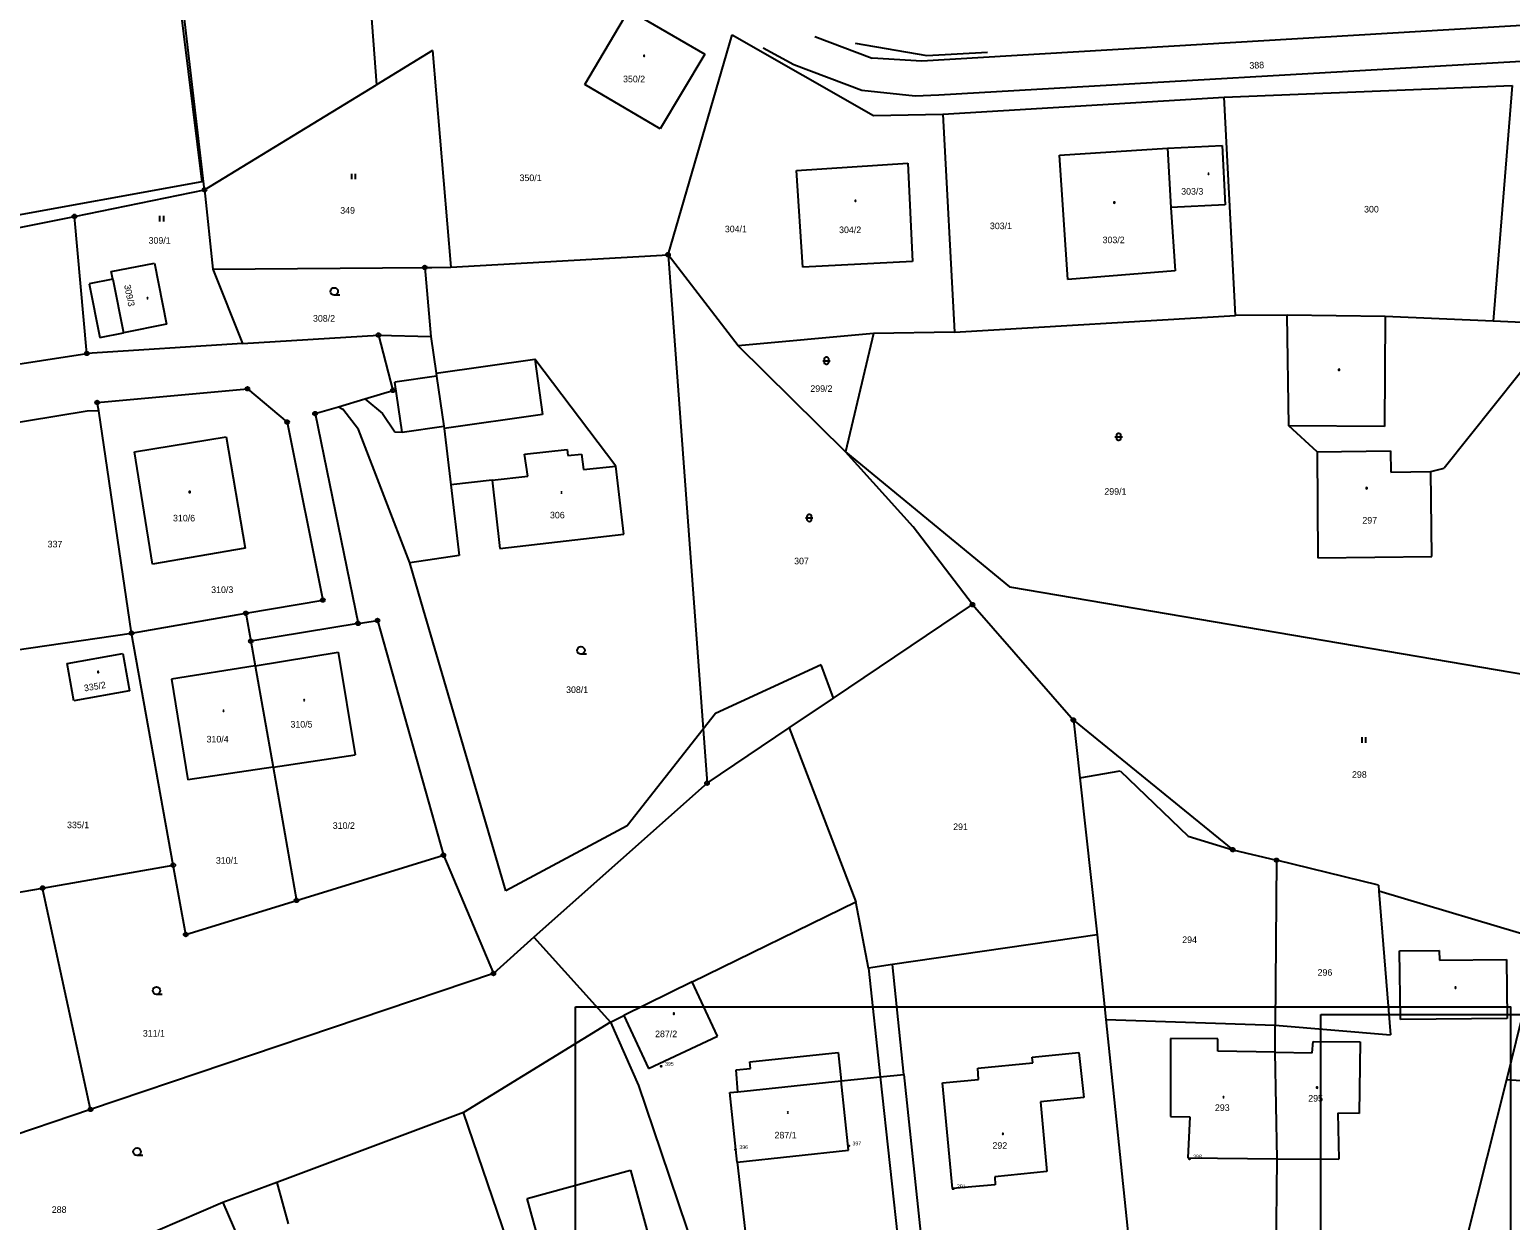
# Model space of a CAD drawing. Extents: x -454285 to -453563, y -1108687 to -1108249.
# Drawn here: x -454026.3 to -453869.2, y -1108463.6 to -1108337.2 of the extents above; entities that cross this region are included whole.
import ezdxf

# ---------------------------------------------------------------- set-up
doc = ezdxf.new("R2010")
doc.units = 0
for name, color, linetype in [('1', 7, 'Continuous'), ('14', 7, 'Continuous'), ('15', 7, 'Continuous'), ('16', 7, 'Continuous'), ('2', 7, 'Continuous'), ('23', 7, 'Continuous'), ('25', 7, 'Continuous'), ('28', 7, 'Continuous'), ('BODY_T1_2018', 7, 'Continuous'), ('CISLA_T1_2018', 7, 'Continuous'), ('rámy', 7, 'Continuous')]:
    doc.layers.add(name, color=color, linetype=linetype)

# ---------------------------------------------------------------- blocks, each defined once
blk = doc.blocks.new('Z402')
for start, end in [(0, 180), (180, 0)]:
    blk.add_arc((0, 0), 0.15, start, end)
blk = doc.blocks.new('Z105')
for radius in [0.5, 0.01]:
    blk.add_circle((0, 0), radius)
blk = doc.blocks.new('Z3040')
blk.add_line((1.5, 0), (0, 0))
blk.add_circle((0, 1), 1)
blk = doc.blocks.new('Z3060')
for p, q in [((-0.5, 1.5), (-0.5, 0)), ((0.5, 1.5), (0.5, 0))]:
    blk.add_line(p, q)
blk = doc.blocks.new('Z3160')
for p, q in [((-1, 1), (1, 1)), ((-0.5, 1.6), (-0.4, 1.8)), ((-0.5, 0.4), (-0.5, 1.6)), ((-0.4, 0.2), (-0.5, 0.4)), ((-0.4, 1.8), (-0.3, 1.9)), ((-0.3, 0.1), (-0.4, 0.2)), ((-0.3, 1.9), (-0.1, 2)), ((-0.1, 0), (-0.3, 0.1)), ((-0.1, 2), (0.1, 2)), ((0.1, 0), (-0.1, 0)), ((0.1, 2), (0.3, 1.9)), ((0.3, 0.1), (0.1, 0)), ((0.3, 1.9), (0.4, 1.8)), ((0.4, 0.2), (0.3, 0.1)), ((0.4, 1.8), (0.5, 1.6)), ((0.5, 0.4), (0.4, 0.2)), ((0.5, 1.6), (0.5, 0.4))]:
    blk.add_line(p, q)
blk = doc.blocks.new('POINT_DISPLAY')
for p, q in [((-0.1, 0), (0.1, 0)), ((0, -0.1), (0, 0.1))]:
    blk.add_line(p, q)
blk.add_circle((0, 0), 0.05)
blk = doc.blocks.new('t1_2018')
at = {"layer": 'BODY_T1_2018'}
for p in [(-453959.29, -1108447.2), (-453951.4, -1108456.05), (-453939.4, -1108455.65), (-453903.26, -1108457.04), (-453928.32, -1108460.2)]:
    blk.add_blockref('POINT_DISPLAY', p, dxfattribs=at)
at = {"layer": 'CISLA_T1_2018'}
for s, p in [('395', (-453958.89, -1108447.14)), ('397', (-453939, -1108455.59)), ('396', (-453951, -1108455.99)), ('398', (-453902.86, -1108456.98)), ('201', (-453927.92, -1108460.14))]:
    blk.add_text(s, height=0.4, dxfattribs=at).set_placement(p)

msp = doc.modelspace()

# ---------------------------------------------------------------- linework, layer by layer
at = {"layer": '1'}
for p, q in [((-454007.73, -1108354.18), (-454012.57, -1108313.19)), ((-453990.72, -1108326.88), (-453989.5, -1108343.02)), ((-453967.38, -1108342.99), (-453962.71, -1108335.1)), ((-453962.71, -1108335.1), (-453954.65, -1108339.78)), ((-453958.57, -1108361.06), (-453951.77, -1108337.73)), ((-453951.77, -1108337.73), (-453936.77, -1108346.27)), ((-453938.72, -1108338.62), (-453931.11, -1108339.92)), ((-453983.57, -1108339.38), (-453989.5, -1108343.02)), ((-453983.57, -1108339.38), (-453981.6, -1108362.39)), ((-453954.65, -1108339.78), (-453959.4, -1108347.71)), ((-453931.11, -1108339.92), (-453924.66, -1108339.55)), ((-454007.73, -1108354.18), (-453989.5, -1108343.02)), ((-453959.4, -1108347.71), (-453967.38, -1108342.99)), ((-453899.58, -1108344.34), (-453869.02, -1108343.11)), ((-453869.02, -1108343.11), (-453871.03, -1108368.12)), ((-453929.41, -1108346.16), (-453899.58, -1108344.34)), ((-453898.37, -1108367.53), (-453899.58, -1108344.34)), ((-453936.77, -1108346.27), (-453929.41, -1108346.16)), ((-453929.41, -1108346.16), (-453928.17, -1108369.27)), ((-453917.03, -1108350.48), (-453905.58, -1108349.76)), ((-453905.58, -1108349.76), (-453899.77, -1108349.48)), ((-453905.58, -1108349.76), (-453905.22, -1108356.05)), ((-453899.77, -1108349.48), (-453899.45, -1108355.77)), ((-453944.94, -1108352.11), (-453933.12, -1108351.33)), ((-453933.12, -1108351.33), (-453932.65, -1108361.78)), ((-453916.15, -1108363.7), (-453917.03, -1108350.48)), ((-453944.27, -1108362.38), (-453944.94, -1108352.11)), ((-454021.54, -1108356.99), (-454007.73, -1108354.18)), ((-454007.73, -1108354.18), (-454006.85, -1108362.58)), ((-453899.45, -1108355.77), (-453905.22, -1108356.05)), ((-453905.22, -1108356.05), (-453904.77, -1108362.76)), ((-454045.66, -1108361.88), (-454021.54, -1108356.99)), ((-454020.21, -1108371.54), (-454021.54, -1108356.99)), ((-454017.64, -1108362.85), (-454013.04, -1108361.95)), ((-454013.04, -1108361.95), (-454011.76, -1108368.45)), ((-454006.85, -1108362.58), (-453984.38, -1108362.42)), ((-453984.38, -1108362.42), (-453983.63, -1108362.41)), ((-453984.38, -1108362.42), (-453983.74, -1108369.73)), ((-453983.63, -1108362.41), (-453981.6, -1108362.39)), ((-453981.6, -1108362.39), (-453958.57, -1108361.06)), ((-453951.11, -1108370.72), (-453958.57, -1108361.06)), ((-453958.57, -1108361.06), (-453954.85, -1108411.41)), ((-453932.65, -1108361.78), (-453944.27, -1108362.38)), ((-454017.48, -1108363.65), (-454019.99, -1108364.16)), ((-454017.48, -1108363.65), (-454017.64, -1108362.85)), ((-454006.85, -1108362.58), (-454003.7, -1108370.5)), ((-453904.77, -1108362.76), (-453916.15, -1108363.7)), ((-454019.99, -1108364.16), (-454018.83, -1108369.84)), ((-454011.76, -1108368.45), (-454016.34, -1108369.37)), ((-453928.17, -1108369.27), (-453898.37, -1108367.53)), ((-453892.89, -1108367.48), (-453898.37, -1108367.53)), ((-453882.49, -1108367.62), (-453892.89, -1108367.48)), ((-453892.7, -1108379.24), (-453892.89, -1108367.48)), ((-453871.03, -1108368.12), (-453882.49, -1108367.62)), ((-453864.04, -1108368.42), (-453876.25, -1108383.71)), ((-454018.83, -1108369.84), (-454016.34, -1108369.37)), ((-454003.7, -1108370.5), (-453989.28, -1108369.59)), ((-453989.28, -1108369.59), (-453983.74, -1108369.73)), ((-453989.28, -1108369.59), (-453987.75, -1108375.46)), ((-453936.76, -1108369.43), (-453951.11, -1108370.72)), ((-453936.76, -1108369.43), (-453939.73, -1108381.98)), ((-453928.17, -1108369.27), (-453936.76, -1108369.43)), ((-454082.44, -1108381.06), (-454020.21, -1108371.54)), ((-454003.7, -1108370.5), (-454020.21, -1108371.54)), ((-453939.73, -1108381.98), (-453951.11, -1108370.72)), ((-453983.18, -1108373.64), (-453972.71, -1108372.15)), ((-453964.1, -1108383.52), (-453972.71, -1108372.15)), ((-453983.14, -1108373.94), (-453987.54, -1108374.58)), ((-453986.78, -1108379.9), (-453987.54, -1108374.58)), ((-453983.18, -1108373.64), (-453983.14, -1108373.94)), ((-454019.13, -1108376.75), (-454003.17, -1108375.29)), ((-454003.17, -1108375.29), (-453998.97, -1108378.82)), ((-453993.52, -1108377.19), (-453990.72, -1108376.35)), ((-453990.72, -1108376.35), (-453987.75, -1108375.46)), ((-453990.72, -1108376.35), (-453988.86, -1108377.9)), ((-454020.2, -1108377.66), (-454048.37, -1108382.31)), ((-454018.94, -1108377.64), (-454020.2, -1108377.66)), ((-454018.94, -1108377.64), (-454019.13, -1108376.75)), ((-454015.47, -1108401.22), (-454018.94, -1108377.64)), ((-453996.01, -1108377.93), (-453993.52, -1108377.19)), ((-453996.01, -1108377.93), (-453991.45, -1108400.19)), ((-453993.52, -1108377.19), (-453993.07, -1108377.45)), ((-453991.41, -1108379.6), (-453993.07, -1108377.45)), ((-453988.86, -1108377.9), (-453987.56, -1108379.86)), ((-453998.97, -1108378.82), (-453995.19, -1108397.71)), ((-453985.96, -1108393.75), (-453991.41, -1108379.6)), ((-453889.72, -1108381.97), (-453892.7, -1108379.24)), ((-454015.17, -1108381.98), (-454005.44, -1108380.38)), ((-454005.44, -1108380.38), (-454003.41, -1108392.2)), ((-453987.56, -1108379.86), (-453986.78, -1108379.9)), ((-454013.27, -1108393.89), (-454015.17, -1108381.98)), ((-453939.73, -1108381.98), (-453922.36, -1108396.3)), ((-453932.58, -1108389.95), (-453939.73, -1108381.98)), ((-453889.72, -1108381.97), (-453889.65, -1108393.25)), ((-453963.27, -1108390.72), (-453964.1, -1108383.52)), ((-453877.66, -1108384.07), (-453876.25, -1108383.71)), ((-453877.53, -1108393.08), (-453877.66, -1108384.07)), ((-453977.24, -1108384.99), (-453981.61, -1108385.48)), ((-453981.61, -1108385.48), (-453980.73, -1108392.98)), ((-453977.24, -1108384.99), (-453976.4, -1108392.24)), ((-453976.4, -1108392.24), (-453963.27, -1108390.72)), ((-453926.27, -1108398.2), (-453932.58, -1108389.95)), ((-454003.41, -1108392.2), (-454013.27, -1108393.89)), ((-453980.73, -1108392.98), (-453985.96, -1108393.75)), ((-453889.65, -1108393.25), (-453877.53, -1108393.08)), ((-453922.36, -1108396.3), (-453863.2, -1108406.37)), ((-454003.35, -1108399.12), (-453995.19, -1108397.71)), ((-453941.01, -1108408.12), (-453926.27, -1108398.2)), ((-453926.27, -1108398.2), (-453915.57, -1108410.45)), ((-454015.47, -1108401.22), (-454003.35, -1108399.12)), ((-454003.35, -1108399.12), (-454002.83, -1108402.07)), ((-453991.45, -1108400.19), (-454002.83, -1108402.07)), ((-453991.45, -1108400.19), (-453989.38, -1108399.89)), ((-453989.38, -1108399.89), (-453982.4, -1108424.79)), ((-454044.83, -1108405.52), (-454015.47, -1108401.22)), ((-454011.05, -1108425.86), (-454015.47, -1108401.22)), ((-454022.31, -1108404.45), (-454016.4, -1108403.39)), ((-454016.4, -1108403.39), (-454015.69, -1108407.36)), ((-454002.83, -1108402.07), (-454002.37, -1108404.69)), ((-454002.37, -1108404.69), (-453993.55, -1108403.25)), ((-453993.55, -1108403.25), (-453991.74, -1108414.13)), ((-454021.6, -1108408.41), (-454022.31, -1108404.45)), ((-454002.37, -1108404.69), (-454011.24, -1108406.13)), ((-454002.37, -1108404.69), (-454000.47, -1108415.44)), ((-454011.24, -1108406.13), (-454009.49, -1108416.78)), ((-454015.69, -1108407.36), (-454021.6, -1108408.41)), ((-453945.72, -1108411.29), (-453941.01, -1108408.12)), ((-453915.57, -1108410.45), (-453914.89, -1108416.57)), ((-453915.57, -1108410.45), (-453898.66, -1108424.21)), ((-453954.85, -1108411.41), (-453954.43, -1108417.15)), ((-453954.43, -1108417.15), (-453945.72, -1108411.29)), ((-453945.72, -1108411.29), (-453938.63, -1108429.73)), ((-454000.47, -1108415.44), (-453991.74, -1108414.13)), ((-454000.47, -1108415.44), (-454009.49, -1108416.78)), ((-454000.47, -1108415.44), (-453997.98, -1108429.59)), ((-453954.43, -1108417.15), (-453972.79, -1108433.51)), ((-453914.89, -1108416.57), (-453913.03, -1108433.25)), ((-453997.98, -1108429.59), (-453982.4, -1108424.79)), ((-453982.4, -1108424.79), (-453977.09, -1108437.35)), ((-453898.66, -1108424.21), (-453894.01, -1108425.33)), ((-453894.01, -1108425.33), (-453894.15, -1108442.84)), ((-453883.2, -1108427.98), (-453894.01, -1108425.33)), ((-454024.91, -1108428.28), (-454011.05, -1108425.86)), ((-454009.73, -1108433.21), (-454011.05, -1108425.86)), ((-454040.76, -1108431.04), (-454024.91, -1108428.28)), ((-454019.82, -1108451.78), (-454024.91, -1108428.28)), ((-453883.2, -1108427.98), (-453883.15, -1108428.6)), ((-454009.73, -1108433.21), (-453997.98, -1108429.59)), ((-453956, -1108438.24), (-453938.63, -1108429.73)), ((-453937.31, -1108436.78), (-453938.63, -1108429.73)), ((-453865.89, -1108433.79), (-453883.15, -1108428.6)), ((-453883.15, -1108428.6), (-453881.93, -1108443.86)), ((-453913.03, -1108433.25), (-453934.77, -1108436.41)), ((-453913.03, -1108433.25), (-453912.11, -1108442.25)), ((-453972.79, -1108433.51), (-453977.09, -1108437.35)), ((-453977.09, -1108437.35), (-454019.82, -1108451.78)), ((-453934.77, -1108436.41), (-453937.31, -1108436.78)), ((-453933.54, -1108448.06), (-453934.77, -1108436.41)), ((-453956, -1108438.24), (-453963.27, -1108441.81)), ((-453953.31, -1108444), (-453956, -1108438.24)), ((-453964.68, -1108442.51), (-453980.28, -1108452.1)), ((-453964.68, -1108442.51), (-453963.27, -1108441.81)), ((-453964.68, -1108442.51), (-453961.7, -1108449.25)), ((-453963.27, -1108441.81), (-453960.65, -1108447.43)), ((-453912.11, -1108442.25), (-453909.31, -1108469.46)), ((-453912.11, -1108442.25), (-453894.15, -1108442.84)), ((-453869.6, -1108448.59), (-453868.09, -1108442.55)), ((-453960.65, -1108447.43), (-453953.31, -1108444)), ((-453894.17, -1108445.7), (-453894.15, -1108442.84)), ((-453894.15, -1108442.84), (-453881.93, -1108443.86)), ((-453893.95, -1108457.01), (-453894.17, -1108445.7)), ((-453940.2, -1108448.76), (-453936.06, -1108448.32)), ((-453939.42, -1108456.12), (-453940.2, -1108448.76)), ((-453936.06, -1108448.32), (-453933.54, -1108448.06)), ((-453933.54, -1108448.06), (-453930.96, -1108472.62)), ((-453873.75, -1108465.15), (-453869.6, -1108448.59)), ((-453869.6, -1108448.59), (-453864.56, -1108448.98)), ((-453961.7, -1108449.25), (-453959.33, -1108456.23)), ((-454019.82, -1108451.78), (-454059.47, -1108465.16)), ((-453980.28, -1108452.1), (-454000.08, -1108459.53)), ((-453969.72, -1108482.96), (-453980.28, -1108452.1)), ((-453959.33, -1108456.23), (-453951.89, -1108478.2)), ((-453951.24, -1108457.36), (-453939.42, -1108456.12)), ((-453973.51, -1108461.22), (-453962.56, -1108458.21)), ((-453962.56, -1108458.21), (-453959.53, -1108469.18)), ((-453951.24, -1108457.36), (-453949.49, -1108472.34)), ((-453894.07, -1108467.77), (-453893.95, -1108457.01)), ((-454000.08, -1108459.53), (-454005.8, -1108461.67)), ((-454000.08, -1108459.53), (-453998.86, -1108463.94)), ((-453970.51, -1108472.16), (-453973.51, -1108461.22)), ((-454005.8, -1108461.67), (-454014.99, -1108465.61)), ((-454005.8, -1108461.67), (-454001.59, -1108471.32))]:
    msp.add_line(p, q, dxfattribs=at)
at = {"layer": '2'}
for p, q in [((-454018.02, -1108273.13), (-454008.01, -1108353.31)), ((-453863.12, -1108336.46), (-453931.66, -1108340.51)), ((-453943.01, -1108337.89), (-453936.91, -1108340.2)), ((-453945.22, -1108340.9), (-453948.48, -1108339.14)), ((-453931.66, -1108340.51), (-453936.91, -1108340.2)), ((-453866.21, -1108340.44), (-453929.83, -1108344.13)), ((-453938, -1108343.64), (-453945.22, -1108340.9)), ((-453932.35, -1108344.23), (-453938, -1108343.64)), ((-453929.83, -1108344.13), (-453932.35, -1108344.23)), ((-454008.01, -1108353.31), (-454045.52, -1108360.12)), ((-454017.48, -1108363.65), (-454016.34, -1108369.37)), ((-453882.49, -1108367.62), (-453882.58, -1108379.31)), ((-453864.04, -1108368.42), (-453871.03, -1108368.12)), ((-453983.74, -1108369.73), (-453983.18, -1108373.64)), ((-453972.71, -1108372.15), (-453971.87, -1108378.01)), ((-453983.14, -1108373.94), (-453982.36, -1108379.25)), ((-453971.87, -1108378.01), (-453982.33, -1108379.5)), ((-453986.78, -1108379.9), (-453982.36, -1108379.25)), ((-453982.36, -1108379.25), (-453982.33, -1108379.5)), ((-453982.33, -1108379.5), (-453981.61, -1108385.48)), ((-453882.58, -1108379.31), (-453892.7, -1108379.24)), ((-453973.78, -1108382.24), (-453969.27, -1108381.72)), ((-453973.44, -1108384.56), (-453973.78, -1108382.24)), ((-453969.27, -1108381.72), (-453969.19, -1108382.39)), ((-453969.19, -1108382.39), (-453967.74, -1108382.22)), ((-453967.74, -1108382.22), (-453967.55, -1108383.87)), ((-453889.72, -1108381.97), (-453881.92, -1108381.86)), ((-453881.92, -1108381.86), (-453881.89, -1108384.13)), ((-453977.24, -1108384.99), (-453973.44, -1108384.56)), ((-453967.55, -1108383.87), (-453964.1, -1108383.52)), ((-453881.89, -1108384.13), (-453877.66, -1108384.07)), ((-453984.74, -1108397.92), (-453985.96, -1108393.75)), ((-453975.77, -1108428.58), (-453984.74, -1108397.92)), ((-453942.33, -1108404.6), (-453953.54, -1108409.74)), ((-453941.01, -1108408.12), (-453942.33, -1108404.6)), ((-453953.54, -1108409.74), (-453954.85, -1108411.41)), ((-453954.85, -1108411.41), (-453962.91, -1108421.67)), ((-453914.89, -1108416.57), (-453910.59, -1108415.84)), ((-453910.59, -1108415.84), (-453903.4, -1108422.78)), ((-453962.91, -1108421.67), (-453975.77, -1108428.58)), ((-453903.4, -1108422.78), (-453898.66, -1108424.21)), ((-453972.79, -1108433.51), (-453964.68, -1108442.51)), ((-453880.96, -1108434.95), (-453876.75, -1108434.91)), ((-453880.88, -1108442.25), (-453880.96, -1108434.95)), ((-453876.75, -1108434.91), (-453876.73, -1108435.94)), ((-453876.73, -1108435.94), (-453869.61, -1108435.86)), ((-453869.61, -1108435.86), (-453869.54, -1108442.13)), ((-453937.31, -1108436.78), (-453936.06, -1108448.32)), ((-453869.54, -1108442.13), (-453880.88, -1108442.25)), ((-453949.9, -1108446.74), (-453940.51, -1108445.75)), ((-453940.51, -1108445.75), (-453940.2, -1108448.76)), ((-453919.95, -1108446.22), (-453914.98, -1108445.74)), ((-453914.98, -1108445.74), (-453914.46, -1108450.52)), ((-453900.24, -1108444.3), (-453905.28, -1108444.26)), ((-453905.28, -1108444.26), (-453905.25, -1108452.54)), ((-453900.23, -1108445.58), (-453900.24, -1108444.3)), ((-453894.17, -1108445.7), (-453900.23, -1108445.58)), ((-453894.17, -1108445.7), (-453890.23, -1108445.77)), ((-453890.23, -1108445.77), (-453890.12, -1108444.57)), ((-453890.12, -1108444.57), (-453885.16, -1108444.6)), ((-453885.16, -1108444.6), (-453885.25, -1108452.21)), ((-453949.83, -1108447.42), (-453949.9, -1108446.74)), ((-453925.7, -1108447.4), (-453919.88, -1108446.82)), ((-453925.62, -1108448.59), (-453925.7, -1108447.4)), ((-453919.88, -1108446.82), (-453919.95, -1108446.22)), ((-453951.35, -1108447.58), (-453949.83, -1108447.42)), ((-453951.15, -1108449.91), (-453951.35, -1108447.58)), ((-453951.15, -1108449.91), (-453940.2, -1108448.76)), ((-453936.06, -1108448.32), (-453933.66, -1108470.44)), ((-453929.46, -1108448.96), (-453925.62, -1108448.59)), ((-453928.38, -1108460.18), (-453929.46, -1108448.96)), ((-453952.01, -1108450), (-453951.15, -1108449.91)), ((-453951.24, -1108457.36), (-453952.01, -1108450)), ((-453914.46, -1108450.52), (-453919.05, -1108450.96)), ((-453919.05, -1108450.96), (-453918.38, -1108458.36)), ((-453905.25, -1108452.54), (-453903.21, -1108452.57)), ((-453903.21, -1108452.57), (-453903.41, -1108456.93)), ((-453885.25, -1108452.21), (-453887.51, -1108452.18)), ((-453887.51, -1108452.18), (-453887.41, -1108457.07)), ((-453918.38, -1108458.36), (-453923.9, -1108458.95)), ((-453903.41, -1108456.93), (-453893.95, -1108457.01)), ((-453893.95, -1108457.01), (-453887.41, -1108457.07)), ((-453923.85, -1108459.77), (-453928.38, -1108460.18)), ((-453923.9, -1108458.95), (-453923.85, -1108459.77))]:
    msp.add_line(p, q, dxfattribs=at)
at = {"layer": 'rámy'}
for points in [[(-453968.38, -1108440.9), (-453869.21, -1108440.9), (-453869.21, -1108500.96), (-453968.38, -1108500.96)], [(-453889.31, -1108441.71), (-453790.14, -1108441.71), (-453790.14, -1108501.76), (-453889.31, -1108501.76)]]:
    msp.add_lwpolyline(points, close=True, dxfattribs=at)

# ---------------------------------------------------------------- block references
msp.add_blockref('t1_2018', (0, 0))
at = {"layer": '23', "xscale": 0.4, "yscale": 0.4000000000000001}
for name, p in [('Z3060', (-453991.94, -1108353.06)), ('Z3060', (-454012.3, -1108357.52)), ('Z3040', (-453993.98, -1108365.36)), ('Z3160', (-453941.76, -1108372.71)), ('Z3160', (-453910.77, -1108380.79)), ('Z3160', (-453943.59, -1108389.4)), ('Z3040', (-453967.81, -1108403.46)), ('Z3060', (-453884.77, -1108412.86)), ('Z3040', (-454012.83, -1108439.57)), ('Z3040', (-454014.89, -1108456.67))]:
    msp.add_blockref(name, p, dxfattribs=at)
at = {"layer": '25', "xscale": 0.4, "yscale": 0.4000000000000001}
for p in [(-453961.09, -1108339.96), (-453901.23, -1108352.47), (-453938.67, -1108355.35), (-453911.22, -1108355.53), (-454013.79, -1108365.68), (-453887.39, -1108373.27), (-453884.45, -1108385.84), (-454009.31, -1108386.24), (-453969.87, -1108386.3), (-454019.01, -1108405.35), (-454005.72, -1108409.48), (-453997.17, -1108408.34), (-453875.03, -1108438.86), (-453957.96, -1108441.61), (-453899.64, -1108450.47), (-453889.73, -1108449.46), (-453945.86, -1108452.11), (-453923.06, -1108454.38)]:
    msp.add_blockref('Z402', p, dxfattribs=at)
at = {"layer": '28', "xscale": 0.4, "yscale": 0.4000000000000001}
for p in [(-454007.73, -1108354.18), (-454021.54, -1108356.99), (-453958.57, -1108361.06), (-453984.38, -1108362.42), (-453989.28, -1108369.59), (-454020.21, -1108371.54), (-454003.17, -1108375.29), (-454019.13, -1108376.75), (-453987.75, -1108375.46), (-453996.01, -1108377.93), (-453998.97, -1108378.82), (-453995.19, -1108397.71), (-453926.27, -1108398.2), (-454003.35, -1108399.12), (-453991.45, -1108400.19), (-453989.38, -1108399.89), (-454015.47, -1108401.22), (-454002.83, -1108402.07), (-453915.57, -1108410.45), (-453954.43, -1108417.15), (-453982.4, -1108424.79), (-453898.66, -1108424.21), (-453894.01, -1108425.33), (-454011.05, -1108425.86), (-454024.91, -1108428.28), (-453997.98, -1108429.59), (-454009.73, -1108433.21), (-453977.09, -1108437.35), (-454019.82, -1108451.78)]:
    msp.add_blockref('Z105', p, dxfattribs=at)

# ---------------------------------------------------------------- texts
at = {"layer": '14'}
for s, p in [('350/1', (-453974.32, -1108353.25)), ('349', (-453993.34, -1108356.71)), ('300', (-453884.73, -1108356.58)), ('303/1', (-453924.42, -1108358.35)), ('309/1', (-454013.67, -1108359.9)), ('304/1', (-453952.54, -1108358.68)), ('308/2', (-453996.23, -1108368.17)), ('299/2', (-453943.47, -1108375.62)), ('299/1', (-453912.28, -1108386.54)), ('337', (-454024.38, -1108392.13)), ('307', (-453945.19, -1108393.92)), ('310/3', (-454007.03, -1108396.97)), ('308/1', (-453969.38, -1108407.58)), ('298', (-453886.01, -1108416.58)), ('335/1', (-454022.32, -1108421.93)), ('310/2', (-453994.13, -1108422)), ('291', (-453928.32, -1108422.13)), ('310/1', (-454006.53, -1108425.7)), ('294', (-453904.02, -1108434.12)), ('296', (-453889.66, -1108437.59)), ('311/1', (-454014.28, -1108444.05)), ('288', (-454023.94, -1108462.76))]:
    msp.add_text(s, height=0.7, dxfattribs=at).set_placement(p)
at = {"layer": '15'}
for s, p in [('350/2', (-453963.34, -1108342.76)), ('303/3', (-453904.13, -1108354.69)), ('304/2', (-453940.42, -1108358.77)), ('303/2', (-453912.47, -1108359.84)), ('310/6', (-454011.08, -1108389.37)), ('306', (-453971.09, -1108389.05)), ('297', (-453884.91, -1108389.6)), ('310/5', (-453998.62, -1108411.25)), ('310/4', (-454007.52, -1108412.83)), ('287/2', (-453959.94, -1108444.11)), ('295', (-453890.65, -1108450.95)), ('293', (-453900.55, -1108451.94)), ('287/1', (-453947.27, -1108454.86)), ('292', (-453924.15, -1108455.96))]:
    msp.add_text(s, height=0.7, dxfattribs=at).set_placement(p)
for s, rotation, p in [('309/3', 281.322, (-454016.27, -1108364.31)), ('335/2', 9.342, (-454020.47, -1108407.42))]:
    msp.add_text(s, height=0.7, rotation=rotation, dxfattribs=at).set_placement(p)
at = {"layer": '16'}
msp.add_text('388', height=0.7, rotation=2.574, dxfattribs=at).set_placement((-453896.88, -1108341.33))

doc.saveas('drawing.dxf')
